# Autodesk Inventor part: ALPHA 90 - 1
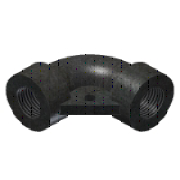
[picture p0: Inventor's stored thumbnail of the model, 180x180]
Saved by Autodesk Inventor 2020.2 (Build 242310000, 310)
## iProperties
Manager: www.cadconsulting.pl
Company: Fabian Stasiak CAD Consulting
Created: 2014-09
Part Number: ALPHA 90 - 1
Material: Stal
Description: Kolanko stalowe gwint. kąt 90, ALPHA
Document SubType Name: Modeling
Standard: ALPHA-010102
Designer: F.Stasiak
Manufacturer: ALPHA
Standards Organization: ANSI
Language: pl-PL
Size Designation: 1
Categories: <MemberInstance><Categories><Category DisplayName="Rury cienko- i grubościenne" InternalName="4347fa0f-2144-441d-94cd-e3e15c92b736" Mnemonic="TUBEANDPIPE"><Cate
Density: 7.85 g/cm^3
Appearance: Płyta
Catalog Web Link: www.expertbooks.pl
IsCustomPart: 0
Author: F.Stasiak
Subject: Zbiór ćwiczeń. Autodesk Inventor 2020. Kurs Professional
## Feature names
1. Przeciągnięcie1
2. Wyciągnięcie proste1 [Extrusion]
3. Wyciągnięcie proste2 [Extrusion]
4. Wyciągnięcie proste5 [Extrusion]
## Parameters: d0 = 74.2315 mm, d1 = 74.2315 mm, d2 = 37.11575 mm, d4 = 0, d5 = 0, d6 = 45.974 mm, d7 = 29.6926 mm, d9 = 20.828 mm, d10 = 0, d11 = 45.974 mm, d12 = 20.828 mm, d13 = 0, d19 = 19.8628 mm, d20 = 0, d21 = 19.8628 mm, d22 = 0, ID = 29.6926 mm, OD = 45.974 mm, GL = 20.828 mm, G = 3.683 mm, d23 = 3.683 mm, d24 = 6.35 mm, d26 = 7.366 mm, d27 = 0
